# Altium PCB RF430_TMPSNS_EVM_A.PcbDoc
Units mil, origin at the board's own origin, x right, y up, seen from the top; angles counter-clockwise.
Board outline 1256 x 1256 mil, 2 copper layers (Top Layer, Bottom Layer), stack 62 mil thick; 41 components, 25 nets, 78 pads, 14 vias.
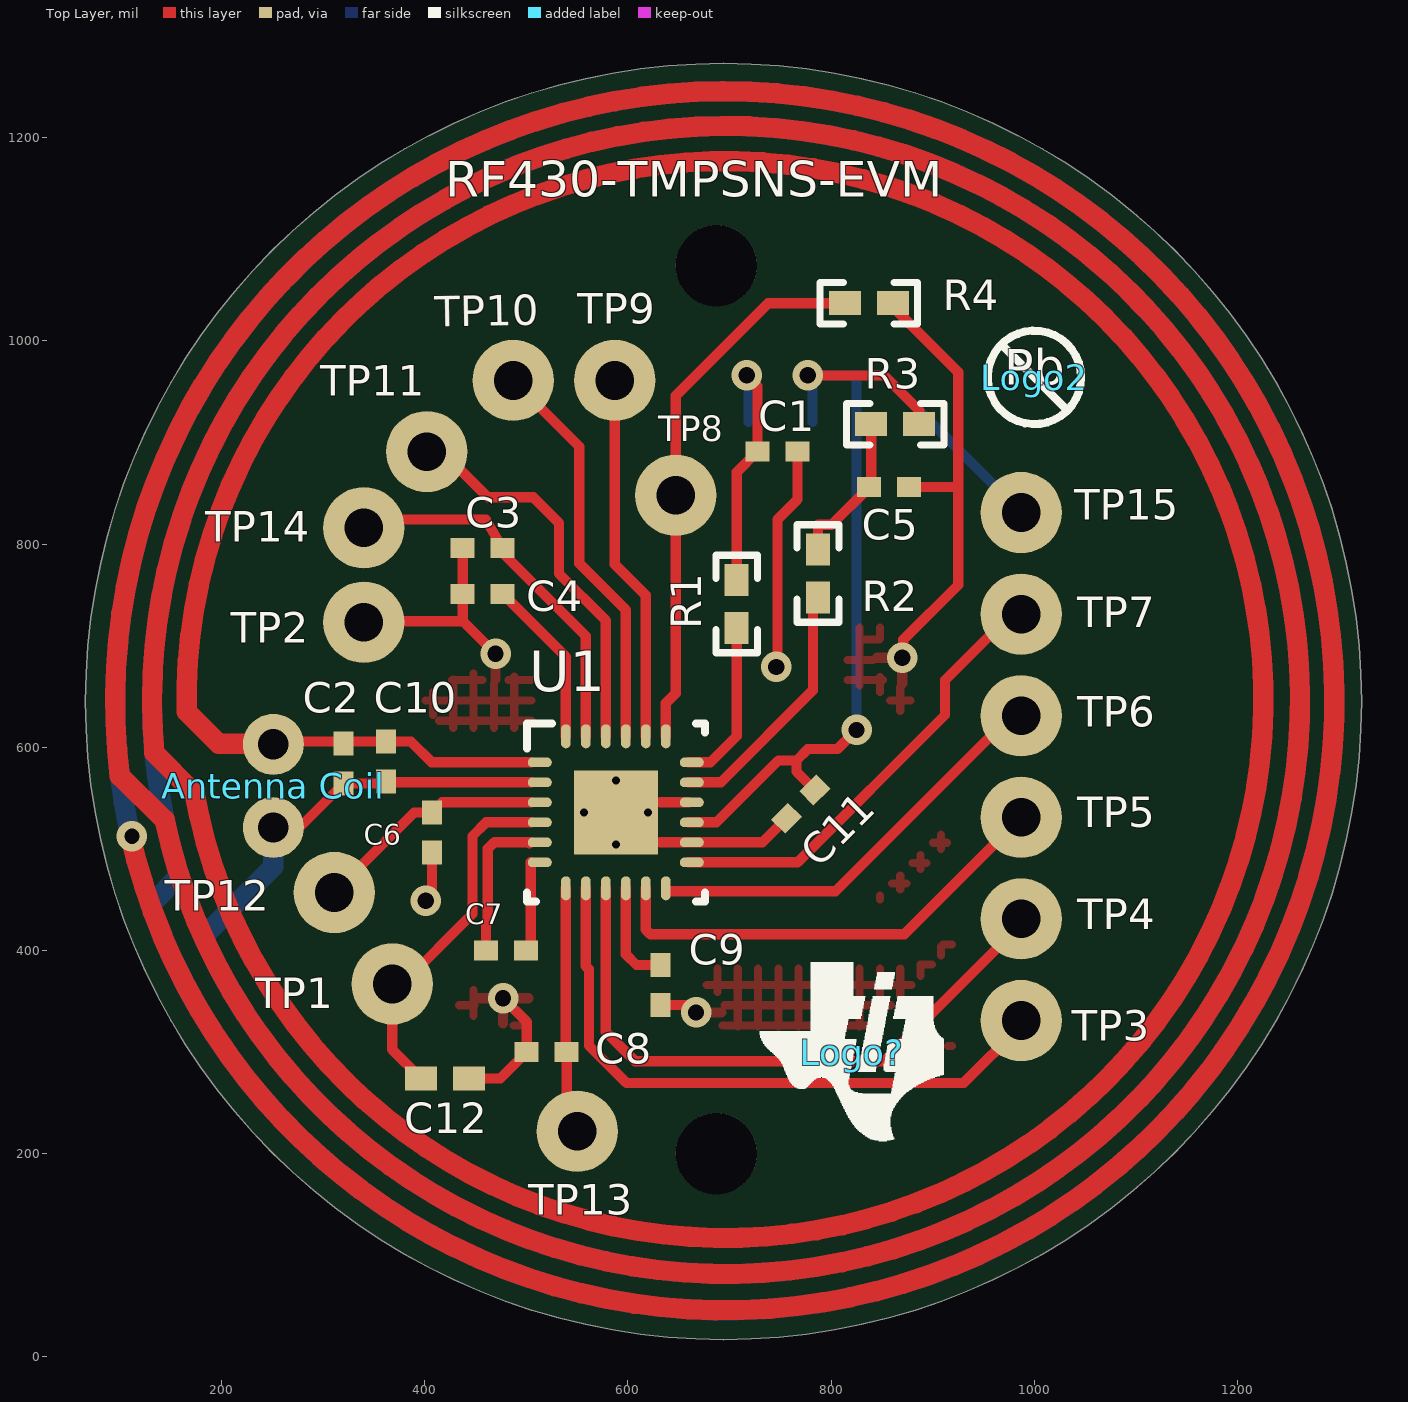
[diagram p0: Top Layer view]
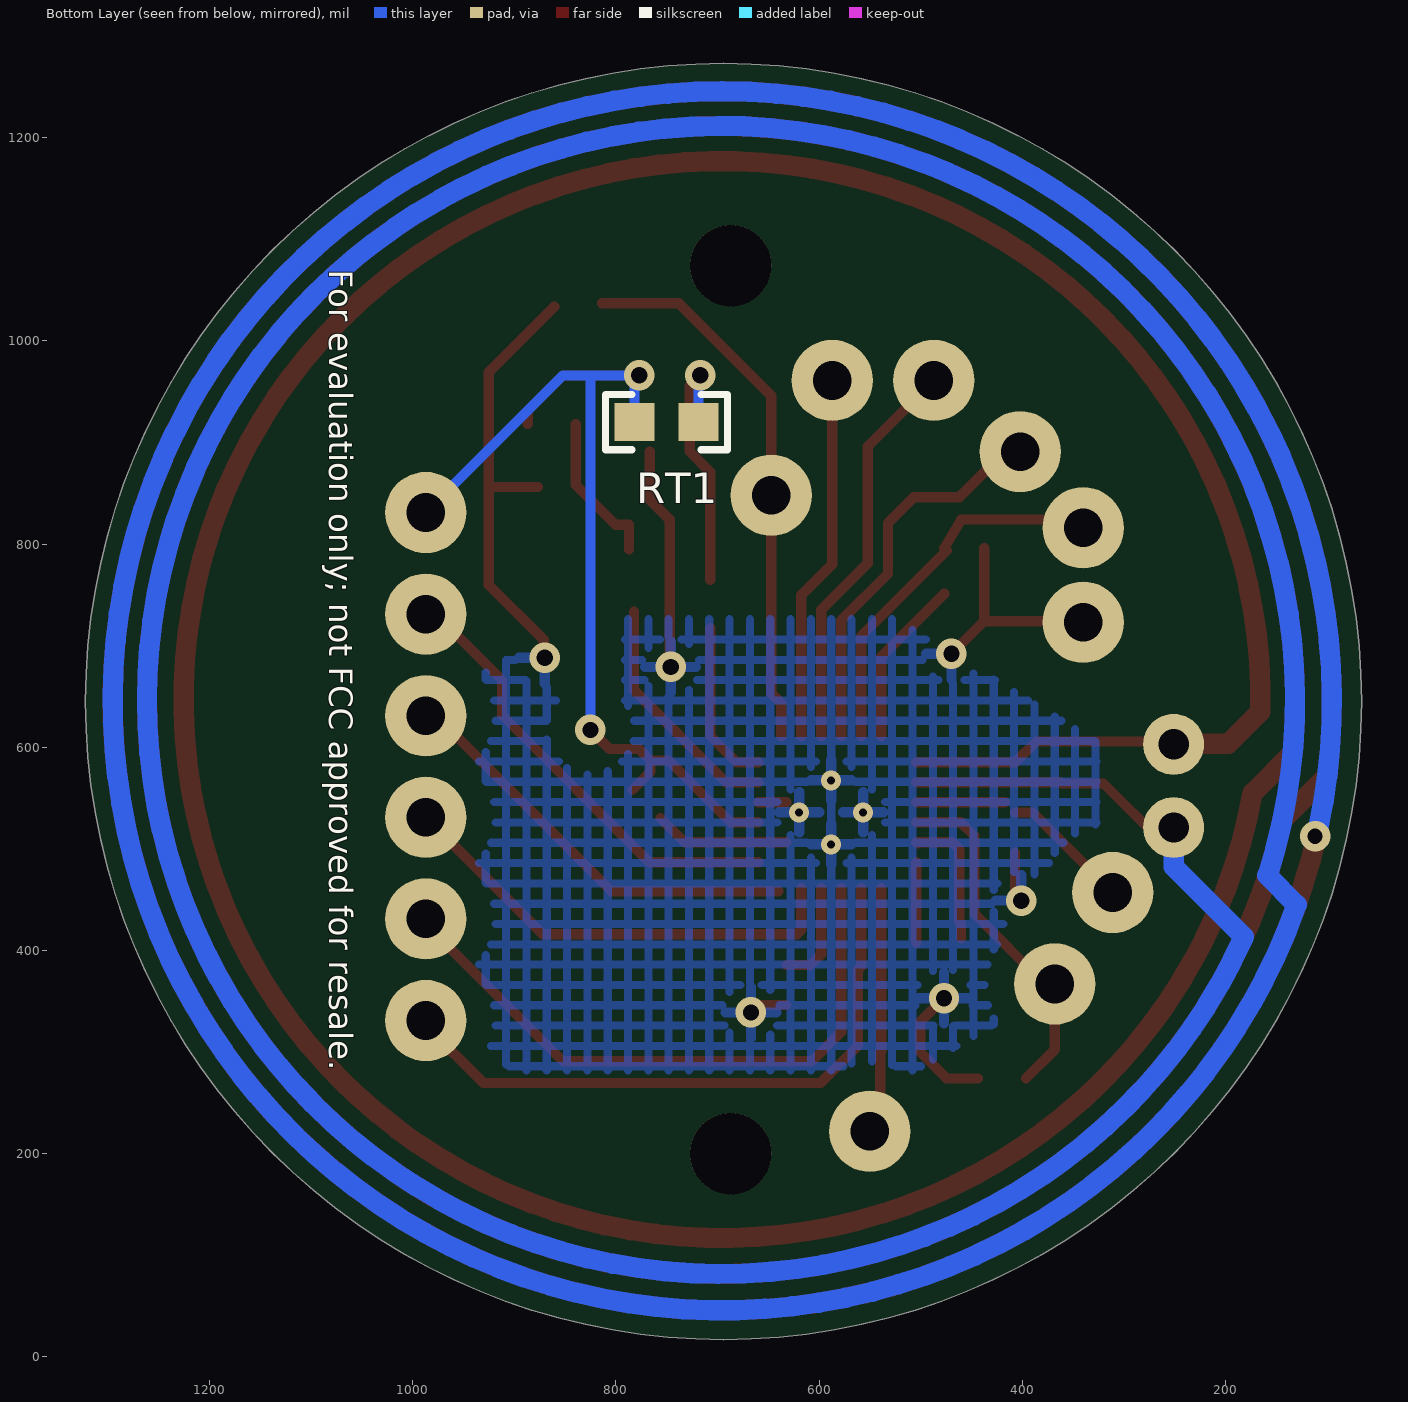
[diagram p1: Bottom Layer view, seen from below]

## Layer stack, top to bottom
Top Solder: solder mask 0.4, Solder Resist, Dk 3.5
Top Layer: signal copper 1.4
Dielectric1: core 59.2, FR-4, Dk 4.8
Bottom Layer: signal copper 1.4
Bottom Solder: solder mask 0.4, Solder Resist, Dk 3.5

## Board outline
694.02,17 cw(c694.02,645) 66.02,645 cw(c694.02,645) 694.02,1273 cw(c694.02,645) 1322.02,645 cw(c694.02,645)

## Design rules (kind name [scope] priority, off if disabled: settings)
AcuteAngle [All] p1: minimum=4.50000000000000E+0001 checktracksonly=FALSE
AssemblyTestPointUsage [All] p1: valid=2
BoardOutlineClearance BoardOutlineClearance_MountingHoles [OnCopper and InComponentClass('Mounting Holes')] p1: gap=40
BoardOutlineClearance BoardOutlineClearance_Poly [OnCopper and InPoly] p2: gap=25
BoardOutlineClearance [OnCopper and Not InComponentClass('Logo') and not InComponentClass('FiducialMark') and not InRegion(1000,500,4000,800)] p3: gap=15
Clearance Clearance_Keepouts [((IsTrack Or IsArc) And Not InPoly) And IsFree and IsKeepOut vs ((IsTrack Or IsArc) And Not InPoly) And IsFree and IsKeepOut] p1: gap=0
Clearance Clearance_Poly [InPolygon] p2: gap=25
Clearance [All] p3: gap=5
ComponentClearance ComponentClearance_MountingHoles_FiducialMarks [InComponentClass('Mounting Holes') vs InComponentClass('FiducialMark')] p1: gap=50 collisioncheckmode=3 verticalgap=10 showdistances=FALSE
ComponentClearance ComponentClearance_Shunt [InComponentClass('Header') vs InComponentClass('Shunt')] p2: gap=0 collisioncheckmode=3 verticalgap=0 showdistances=FALSE
ComponentClearance ComponentClearance_Logo [InComponentClass('Logo')] p3 off: gap=10 collisioncheckmode=3 verticalgap=10 showdistances=FALSE
ComponentClearance ComponentClearance_ScrewToNut [(HasFootprint('NY PMS 440 0025 PH')) vs (HasFootprint('Keystone_1902C'))] p4: gap=5 collisioncheckmode=3 verticalgap=10 showdistances=FALSE
ComponentClearance ComponentClearance_MountingHoles [InComponentClass('Mounting Holes')] p5: gap=250 collisioncheckmode=3 verticalgap=100000 showdistances=FALSE
ComponentClearance ComponentClearance_SmallPassives [HasFootprint('0201*') or HasFootprint('0402*') or HasFootprint('0508') or HasFootprint('0603*') or HasFootprint('0612') or HasFootprint('0805*') or HasFootprint('0815*') or HasFootprint('0830*') or HasFootprint('1206*') or HasFootprint('1210*') or HasFootprint('1808*') or HasFootprint('1812*') or HasFootprint('1825*') or HasFootprint('2010*') or HasFootprint('2220*') or HasFootprint('2225*') or HasFootprint('2512*') or HasFootprint('2728*') or HasFootprint('3518*') vs HasFootprint('0201*') or HasFootprint('0402*') or HasFootprint('0508') or HasFootprint('0603*') or HasFootprint('0612') or HasFootprint('0805*') or HasFootprint('0815*') or HasFootprint('0830*') or HasFootprint('1206*') or HasFootprint('1210*') or HasFootprint('1808*') or HasFootprint('1812*') or HasFootprint('1825*') or HasFootprint('2010*') or HasFootprint('2220*') or HasFootprint('2225*') or HasFootprint('2512*') or HasFootprint('2728*') or HasFootprint('3518*')] p6: gap=14.96 collisioncheckmode=3 verticalgap=10 showdistances=FALSE
ComponentClearance ComponentClearance_THtoSMT [IsThruComponent vs IsSMTComponent] p7 off: gap=3 collisioncheckmode=3 verticalgap=30 showdistances=TRUE
ComponentClearance ComponentClearance_THtoTH [IsThruComponent vs IsThruComponent] p8 off: gap=5 collisioncheckmode=3 verticalgap=30 showdistances=FALSE
ComponentClearance [All] p9 off: gap=30 collisioncheckmode=3 verticalgap=10 showdistances=FALSE
DiffPairsRouting [All] p1: maxlimit=100 minlimit=10 mostfreqgap=10 toplayer_minwidth=15 toplayer_maxwidth=15 toplayer_prefwidth=15 bottomlayer_minwidth=15 bottomlayer_maxwidth=15 bottomlayer_prefwidth=15 maxuncoupledlength=1000
FabricationTestPointUsage TestPointUsage [All] p1: valid=2 allowmultiple=FALSE
FabricationTestpoint Testpoint [All] p1: side=3 testpointundercomponent=TRUE minsize=40 maxsize=100 preferedsize=60 minholesize=0 maxholesize=40 preferedholesize=32 testpointgrid=1 allowsidetop=TRUE allowsidebottom=TRUE usegrid=TRUE gridtolerance=0.01
FanoutControl Fanout_LCC [IsLCC] p1: bgadir=Out bgaviamode=Centered fanoutstyle=Auto fanoutdirection=Alternating viagrid=1 // Fanout_LCC (Default Rule)
FanoutControl Fanout_BGA [IsBGA] p2: bgadir=Out bgaviamode=Centered fanoutstyle=Auto fanoutdirection=Alternating viagrid=1 // Fanout_BGA (Default Rule)
FanoutControl Fanout_Default [All] p4: bgadir=Out bgaviamode=Centered fanoutstyle=Auto fanoutdirection=Alternating viagrid=1 // Fanout_Default (Default Rule)
FanoutControl Fanout_Small [(CompPinCount < 5)] p5: bgadir=Out bgaviamode=Centered fanoutstyle=Auto fanoutdirection=OutThenIn viagrid=1 // Fanout_Small (Default Rule)
HoleSize [All] p1: absolutevalues=TRUE maxlimit=251 minlimit=7.87 maxpercent=80.000 minpercent=20.000
MinimumAnnularRing MinimumAnnularRing_ThermalPadVias [IsVia and InAnyComponent] p1: minimumring=5
MinimumAnnularRing [All] p2: minimumring=5
MinimumSolderMaskSliver MinimumSolderMaskSliver_Logo [InComponentClass('Logo') vs InComponentClass('Logo')] p1: minsoldermaskwidth=0.7
MinimumSolderMaskSliver [All] p2: minsoldermaskwidth=4
PlaneConnect [All] p1: planeconnectstyle=Relief reliefexpansion=10 reliefentries=4 reliefconductorwidth=10 reliefairgap=10
PolygonConnect [All] p1: connectstyle=Relief reliefconductorwidth=10 reliefentries=4 polygonreliefangle="90 Angle" airgapwidth=10
RoutingVias ThermalPadVias [IsVia and InAnyComponent] p1: holewidth=7.87 width=19.68 viastyle="Through Hole" minholewidth=7.87 minwidth=19.68 maxholewidth=15 maxwidth=35
RoutingVias [All] p2: holewidth=16 width=34 viastyle="Through Hole" minholewidth=7.87 minwidth=26 maxholewidth=40 maxwidth=65
SilkToBoardRegionClearance [Not ((IsComment or IsDesignator) And (Hide <> 'False')) and not InRegion(1000,500,4000,800)] p1:
SilkToSilkClearance SilkToSilkClearance_Pb-FreeLogo [(HasFootprint('Pb-Free_Overlay_Medium') OR HasFootprint('Pb-Free_Overlay_Small')) vs (HasFootprint('Pb-Free_Overlay_Medium') OR HasFootprint('Pb-Free_Overlay_Small'))] p1: silktosilkclearance=0
SilkToSilkClearance [All] p2: silktosilkclearance=3
SilkToSolderMaskClearance SilkToComponentPadClearance [IsPad and InAnycomponent] p1: minsilkscreentomaskgap=3 clearancetoexposedcopper=TRUE
SilkToSolderMaskClearance "Silk to Solder Mask Opening" [All] p2: minsilkscreentomaskgap=3 clearancetoexposedcopper=FALSE
SolderMaskExpansion [All] p1: expansion=1.97
Width [All] p1: maxlimit=100 minlimit=6 preferedwidth=10 checkconnectedcopper=TRUE
15 further rules are at their usual default settings.

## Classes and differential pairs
component class TIDM-TEMPSENSE: "Antenna Coil" C1 C2 C3 C4 C5 C6 C7 C8 C9 C10 C11 C12 R1 R2 R3 R4 RT1 TP1 TP2 TP3 TP4 TP5 TP6 TP7 TP8 TP9 TP10 TP11 TP12 TP13 TP14 TP15 U1
component class Logo: Logo?
component class TIDM-TEMPSENSE_Hardware: Logo2 Logo3 Logo? ZZ1 ZZ2 ZZ3 ZZ4
component class AssemblyNote: ZZ1 ZZ2 ZZ3 ZZ4

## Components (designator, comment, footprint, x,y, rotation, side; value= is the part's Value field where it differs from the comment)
"Antenna Coil" "Antenna Coil" PCBComponent_1 696,646 r0 top
C1 "C1005C0G1H220J050BA" 0402#1 747,891 r0 top
C2 "GRM1555C1E3R9CA01D" 0402#1 320,584 r270 top
C3 "885012205037" 0402#1 457,796 r0 top
C4 "885012205037" 0402#1 457,751 r0 top
C5 "C1005C0G1H220J050BA" 0402#1 857,856 r0 top
C6 "C1005X5R1A225K050BC" 0402#1 407,516 r90 top
C7 "885012205031" 0402#1 480,400 r0 top
C8 "885012205037" 0402#1 520,300 r0 top
C9 "885012205037" 0402#1 632,366 r90 top
C10 "GRM1555C1E330JA01D" 0402#1 362,586 r270 top
C11 "C1005X7S1A105K050BC" 0402#1 770,544 r45 top
C12 "885012205037" 0402#2 420,274 r0 top
Logo2 "Pb-Free Symbol" Pb-Free_Overlay_Small 1000,964 r0 top
Logo3 "FCC disclaimer" FCC_disclaimer 690,2314 r0 top
Logo? "Texas Instruments" TI_Symbol_Overlay_Small 820,300 r0 top
R1 "CRCW04021K00FKED" 0402#2 707,741 r90 top
R2 "CRCW04021K00FKED" 0402#2 787,771 r90 top
R3 "CRCW0402100KJNED" 0402#2 863,918 r180 top
R4 "CRCW040210K0JNED" 0402#2 837,1037 r180 top
RT1 "ERT-J1VS104FA" 0603 750,920 r180 bottom
TP1 "TESTPOINT" TESTPOINT#1 368,367 r0 top
TP2 "TESTPOINT" TESTPOINT#2 339,723 r0 top
TP3 "TESTPOINT" TESTPOINT#3 987,326 r90 top
TP4 "TESTPOINT" TESTPOINT#4 987,431 r90 top
TP5 "TESTPOINT" TESTPOINT#5 987,541 r90 top
TP6 "TESTPOINT" TESTPOINT#6 987,646 r90 top
TP7 "TESTPOINT" TESTPOINT#7 987,751 r0 top
TP8 "TESTPOINT" TESTPOINT#4 647,848 r90 top
TP9 "TESTPOINT" TESTPOINT#4 587,961 r90 top
TP10 "TESTPOINT" TESTPOINT#3 487,956 r90 top
TP11 "TESTPOINT" TESTPOINT#4 402,891 r90 top
TP12 "TESTPOINT" TESTPOINT#4 311,457 r90 top
TP13 "TESTPOINT" TESTPOINT#4 550,222 r90 top
TP14 "TESTPOINT" TESTPOINT#4 340,816 r90 top
TP15 "TESTPOINT" TESTPOINT#8 993,853 r90 top
U1 "RF430FRL152HCRGER" RGE0024C 588,535.95 r0 top
ZZ1 "This Assembly Note is for PCB labels only" AssemblyNoteLabel 185,3938 r0 top
ZZ2 "These assemblies are ESD sensitive, ESD precautions shall be observed." AssemblyNote 185,3829.11 r0 top
ZZ3 "These assemblies must be clean and free from flux and all contaminants. Use of no clean flux is not acceptable." AssemblyNote 185,3740.56 r0 top
ZZ4 "These assemblies must comply with workmanship standards IPC-A-610 Class 2, unless otherwise specified." AssemblyNote 185,3652 r0 top

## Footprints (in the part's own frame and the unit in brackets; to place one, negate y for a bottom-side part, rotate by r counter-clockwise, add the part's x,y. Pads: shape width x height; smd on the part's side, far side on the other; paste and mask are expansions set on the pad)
0402#1 [mm] "Chip Capacitor, Body 1.0x0.5mm, IPC High Density"
  rect 0.6x0.5 smd: 1(-0.5,0) 2(0.5,0)
  body extent -0.55,-0.3 0.55,0.3, height 1.3
0402#2 [mm] "0402 from SM-752 data"
  rect 0.8x0.6 smd: 1(-0.6,0) 2(0.6,0)
  body extent -0.55,-0.3 0.55,0.3, height 0.6
0603 [mm] "0603 from SM-752 data"
  rect 1x0.95 smd: 1(-0.8,0) 2(0.8,0)
  silkscreen extent -1.52,-0.69 1.52,0.69, body extent -0.87,-0.47 0.87,0.47, height 1
AssemblyNote [mil] "Assembly Note"
AssemblyNoteLabel [mil] "Assembly Note for PCB Labels"
FCC_disclaimer [mil]
Pb-Free_Overlay_Small [mil]
  silkscreen extent -46,-46 46,46
PCBComponent_1 [mil]
  round 60 hole 30: 1(-445,-43.17) 2(-445,-125)
  Top Layer lines w15: -460.26,-42.5 -452.3,-50.46
  Top Layer lines w20: -596.14,-74.45 cw(c-0.75,-0.24) -586.28,-131.22 ; -595.62,-74.38 -552.64,-117.36 ; -562.45,-51.55 -523.17,-90.83 ; -562.13,-51.23 cw(c0.5,0.5) -552.1,-117.24 ; -530.41,-11.29 cw(c-0.55,0.93) -522.57,-90.73 ; -530.21,-11.29 -499,-42.5 -460.26,-42.5
  Bottom Layer lines w20: -587.16,-127.22 cw(c-0.74,-0.28) -566.17,-201 ; -565.92,-200.92 -537,-172 ; -537.48,-172.15 cw(c0.49,0.54) -514.14,-232.66 -445,-163.52 -445,-125
RGE0024C [mm] "QFN, 24-Leads, Body 4x4mm, Pitch 0.5mm, Thermal Pad 2.1x2.1mm"
  oval 0.6x0.24 smd mask+0.025: 1(-1.9,1.25) 2(-1.9,0.75) 3(-1.9,0.25) 4(-1.9,-0.25) 5(-1.9,-0.75) 6(-1.9,-1.25) 13(1.9,-1.25) 14(1.9,-0.75) 15(1.9,-0.25) 16(1.9,0.25) 17(1.9,0.75) 18(1.9,1.25)
  oval 0.24x0.6 smd mask+0.025: 7(-1.25,-1.9) 8(-0.75,-1.9) 9(-0.25,-1.9) 10(0.25,-1.9) 11(0.75,-1.9) 12(1.25,-1.9) 19(1.25,1.9) 20(0.75,1.9) 21(0.25,1.9) 22(-0.25,1.9) 23(-0.75,1.9) 24(-1.25,1.9)
  rect 2.1x2.1 smd paste-1.05: 25(0,0)
  silkscreen extent -2.22,-2.22 2.22,2.22, body extent -2.07,-2.07 2.07,2.07, height 1.01
TESTPOINT#1 [mil]
  round 80 hole 37.99 paste+5: 1(0,0)
TESTPOINT#2 [mil]
  round 80 hole 37.99: 1(1,0)
TESTPOINT#3 [mil]
  round 80 hole 37.99: 1(5,0)
TESTPOINT#4 [mil]
  round 80 hole 37.99: 1(0,0)
TESTPOINT#5 [mil]
  round 80 hole 37.99: 1(-10,0)
TESTPOINT#6 [mil]
  round 80 hole 37.99: 1(-15,0)
TESTPOINT#7 [mil]
  round 80 hole 37.99: 1(0,-20)
TESTPOINT#8 [mil]
  round 80 hole 37.99: 1(-22,6)
TI_Symbol_Overlay_Small [mil]
  silkscreen extent -90,-88 91,88

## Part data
"Antenna Coil": library part Component_1
C1 C5: "CAP, CERM, 22 pF, 50 V, +/- 5%, C0G/NP0, 0402"
C2: "CAP, CERM, 3.9 pF, 25 V, +/- 5%, C0G/NP0, 0402"
C3 C4 C8 C9 C12: "CAP, CERM, 0.1 µF, 16 V, +/- 10%, X7R, 0402"
C6: "CAP, CERM, 2.2 µF, 10 V, +/- 10%, X5R, 0402"
C7: "CAP, CERM, 0.01 µF, 16 V, +/- 10%, X7R, 0402"
C10: "CAP, CERM, 33 pF, 25 V, +/- 5%, C0G/NP0, 0402"
C11: "CAP, CERM, 1 µF, 10 V, +/- 10%, X7S, 0402"
Logo2: library part Pb-Free
Logo3: library part FCC_disclaimer, "FCC_disclaimer"
Logo?: library part TI_Logo, "Texas Instrument Corporate Signature"
R1 R2: "RES, 1.00 k, 1%, 0.063 W, 0402"
R3: "RES, 100 k, 5%, 0.063 W, 0402"
R4: "RES, 10 k, 5%, 0.063 W, 0402"
RT1: "Thermistor NTC, 100k ohm, 1%, 0603"
TP1 TP2 TP3 TP4 TP5 TP6 TP7 TP8 TP9 TP10 TP11 TP12 TP13 TP14 TP15: "TEST POINT.  No entry in BOM."
U1: "NFC ISO 15693 Sensor Transponder, RGE0024C"
ZZ1: library part AssemblyNoteLabel
ZZ2 ZZ3 ZZ4: library part AssemblyNote

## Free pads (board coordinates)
  round 80 hole 80: 0(687,200) 0(687,1074)

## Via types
v1: diameter 30, hole 16, Top Layer to Bottom Layer, 9 vias
v2: diameter 19.68, hole 7.87, Top Layer to Bottom Layer, 4 vias
v3: diameter 30, hole 15, Top Layer to Bottom Layer, 1 vias

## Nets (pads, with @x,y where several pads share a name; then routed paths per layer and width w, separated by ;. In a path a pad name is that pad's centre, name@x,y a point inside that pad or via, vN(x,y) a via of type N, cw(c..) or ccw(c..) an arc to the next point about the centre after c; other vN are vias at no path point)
ADC0: TP7.1 U1.13 | length 452.6
  Top Layer w10: U1.13@659.76,486.79 767,486.79 912,631.79 912,666 TP7.1@987,741
ANT1: "Antenna Coil.1" C2.1 C10.1 U1.1 | length 250.4
  Top Layer w10: 262.36,605.68 C10.1 386.32,605.68 406.79,585.21 U1.1@504.24,585.21
ANT2: "Antenna Coil.2" C2.2 C10.2 U1.2 | length 264.2
  Top Layer w10: 263.81,508.13 C2.2 361.57,564.31 362.79,565.53 U1.2@504.24,565.53
FLYING_CAP_T1: C7.1 U1.5 | length 135.5
  Top Layer w10: 460.39,411.92 460.39,426.57 462,428.18 462,500 468.47,506.47 504.24,506.47 U1.5@502.94,505.17
FLYING_CAP_T2: C7.2 U1.6 | length 79.3
  Top Layer w10: C7.2@504.24,407.44 U1.6@504.24,486.79
GND: C1.2 C3.1 C4.1 C5.2 C6.1 C8.1 C9.1 C11.1 C12.2 R4.1 TP2.1 U1.14 U1.16 U1.25 | length 1238.7
  Top Layer w10: TP2.1@340,724 437.02,724 437.31,724.3 ; v1@407,455 C6.1 ; C3.1 C4.1 437.32,724.3 ; C12.2 474.32,274 C8.1 500.31,329.69 v1(477,353) ; v1(469.63,691.98) 437.31,724.3 ; C9.1 v1@659.68,346.32 ; 632,506.47 659.76,506.47 732.47,506.47 C11.1 ; 632,545.84 U1.16@659.76,545.84 ; v1@747,679 747,824 766.68,843.68 C1.2 ; R4.1@860.62,1033.59 925,969.21 925,856 ; v1@871,688 871,705.71 925,759.71 925,856 ; C5.2 925,856
  other v1: 667,339 401,449 746,679 870,688
  other v2: 588,504.45 556.5,535.95 619.5,535.95 588,567.45
NetC1_1: C1.1 R1.2 RT1.2 | length 258.6
  Top Layer w10: R1.2 707,870.69 C1.1 727.32,955.68 v1(717,966)
  Bottom Layer w10: RT1.2 v1@718.5,964.5
NetC4_2: C4.2 U1.24 | length 166
  Top Layer w10: C4.2 538.79,688.9 U1.24
NetC5_1: C5.1 R2.2 R3.2 | length 152.9
  Top Layer w10: R2.2 787,819 800.31,819 C5.1 839.38,858.06 R3.2
NetC9_2: C9.2 U1.10 | length 103.5
  Top Layer w10: U1.10 597.84,396.16 608.32,385.68 C9.2
P1.0/MOSI/SDA: TP6.1 U1.12 | length 422.6
  Top Layer w10: U1.12@640.12,458.24 804.24,458.24 TP6.1@987,641
P1.1/MISO/SCL: TP5.1 U1.11 | length 459.6
  Top Layer w10: U1.11 617.53,420.47 622,416 872,416 TP5.1
P1.2/SPI_CLK: TP4.1 U1.9 | length 618
  Top Layer w10: U1.9 578.16,319.84 607,291 852,291 TP4.1@987,426
P1.3/SPI_CS: TP3.1 U1.8 | length 620
  Top Layer w10: U1.8 558.47,384.53 561.5,381.5 561.5,306.5 598.38,269.62 930.62,269.62 TP3.1@987,326
P1.4/TCK: TP11.1 U1.22 | length 408.6
  Top Layer w10: TP11.1@392,916 462,846 506.84,846 532,820.84 532,771 578.16,724.84 U1.22
P1.5/TDI: TP10.1 U1.21 | length 396.2
  Top Layer w10: TP10.1 552,896 552,781 597.84,735.16 U1.21
P1.6/TDO: TP9.1 U1.20 | length 357
  Top Layer w10: TP9.1@577,951 587,941 587,780.07 617.53,749.54 U1.20
P1.7/TMS: R4.2 TP8.1 U1.19 | length 543.4
  Top Layer w10: U1.19 637.21,643.21 647,653 TP8.1 647,946 738,1037 R4.2
SENSOR_REFERENCE_POTENTIAL: C11.2 R3.1 RT1.1 TP15.1 U1.15 | length 1028.2
  Top Layer w10: U1.15@659.76,526.16 687.16,526.16 748,587 765.87,587 ; v1(777,966) 852,966 886.62,931.38 R3.1 ; C11.2 765.87,575.96 765.87,587 ; v1(825,617) 806.1,598.1 776.98,598.1 765.87,587
  Bottom Layer w10: v1(777,966) 852,966 TP15.1 ; RT1.1 v1@781.5,961.5 ; v1(825,617) 825,961
SKIN_TEMPERATURE_REFERENCE: R2.1 U1.17 | length 237
  Top Layer w10: U1.17@659.76,565.53 691.53,565.53 782,656 R2.1@782,733.28
SKIN_TEMPERATURE_THERMISTER: R1.1 U1.18 | length 164.3
  Top Layer w10: U1.18@659.76,585.21 681.21,585.21 707,611 R1.1
VDD2X: C8.2 TP13.1 U1.7 | length 255.2
  Top Layer w10: TP13.1@523.81,209.36 523.81,237.72 TP13.1@534.28,248.19 ; C8.2@538.79,300.9 U1.7 ; TP13.1@539.68,248.19 C8.2
VDDB: C12.1 TP1.1 U1.4 | length 341.8
  Top Layer w10: TP1.1 368,302.38 C12.1 ; TP1.1@378,367 447,436 447,512.69 460.47,526.16 U1.4@504.24,526.16
VDDH: C3.2 TP14.1 U1.23 | length 367
  Top Layer w10: TP14.1@343.32,824 460,824 C3.2 ; C3.2@474.34,793.66 558.47,709.53 U1.23
VDDSW: C6.2 TP12.1 U1.3 | length 215.7
  Top Layer w10: TP12.1 389.69,535.69 C6.2 ; 417.16,545.84 U1.3@504.24,545.84
copper on no net:
  other v3: 111.72,512.28

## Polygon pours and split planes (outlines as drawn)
GND on Bottom Layer "Top Layer-No Net" (hatched 90Degree grid 20 track 8, pour order 0): 506.47,282 898.48,282 1026,359.84 1021.28,362.73 1021.28,616.44 851.25,720.23 841.8,726 586.76,726 525.36,726 412.01,656.81 327,604.91 327,385.79
GND on Top Layer "Top Layer-GND" (hatched 90Degree grid 20 track 8, pour order 2): 348.14,388.05 361.85,388.05 521.78,291 901.05,291 914.76,291 1024.43,357.55 1029,360.32 1029,612.64 1024.43,612.64 850.79,718 540.06,718 512.64,718 339,612.64 343.57,609.86 343.57,390.82

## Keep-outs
Keep-Out Layer:
  text ".Layer_Name" at 577,-858.49 h60

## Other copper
Top Layer:
  text ".Layer_Name" at 577,-858.49 h60
Bottom Layer:
  text ".Layer_Name" at 577,-858.49 h60

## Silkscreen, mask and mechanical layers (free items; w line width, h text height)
Top Overlay:
  text "RF430-TMPSNS-EVM" at 420,1130 h60
  text ".Layer_Name" at 577,-858.49 h60
Bottom Overlay:
  text ".Layer_Name" at 577,-858.49 h60
Top Paste:
  text ".Layer_Name" at 577,-858.49 h60
Bottom Paste:
  text ".Layer_Name" at 577,-858.49 h60
Top Solder:
  text ".Layer_Name" at 577,-858.49 h60
  text ".Layer_Name" at 577,-858.49 h60
Bottom Solder:
  text ".Layer_Name" at 577,-858.49 h60
Drill Guide:
  text ".Layer_Name" at 577,-858.49 h60
M1 Board Outline:
  circle w10: c694.02,645 r628
  text ".Layer_Name" at 577,-858.49 h60
M2 Board Dimensions:
  rectangle: 0,-275 125,-150
  rectangle: 125,-400 500,-275
  lines w7: 0,-275 1000,-275 ; 125,-400 125,-150 ; 250,-400 250,-150 ; 500,-400 500,-150 ; 750,-400 750,-150 ; 0,-400 1000,-400 1000,-150 0,-150 0,-400
  text ".Layer_Name" at 577,-858.49 h60
M3 3D STEP Top:
  text ".Layer_Name" at 577,-858.49 h60
M4 3D STEP Bottom:
  text ".Layer_Name" at 577,-858.49 h60
M5 Assembly Top:
  lines w10: -292,-930.17 6308,-930.17 ; -292,-726.83 6310,-726.83 ; -292,-523.5 -292,-1133.5 3713,-1133.5 6310,-1133.5 6310,-523.5 -291.5,-523.5 -291.5,-1133.5 1284,-1133.5 ; 2173,-1133.5 2173,-523.5 ; 3440,-726.83 3440,-523.5 ; 4280,-726.83 4280,-523.5 ; 4902,-1140 4902,-937.17
  text "COMPONENTS MARKED 'DNP' SHOULD NOT BE POPULATED." at 1153.5,-318.5 h60
  text "ASSEMBLY VARIANT:" at 1153,-434 h60
  text ".VariantName" at 2189,-434 h60
  text "PCB VIEWED FROM TOP SIDE" at -228.5,-655.67 h60
  text "BOARD #:" at 2248,-655.67 h60
  text ".PRJ_Number" at 2793.5,-655.67 h60
  text "REV:" at 3638,-655.67 h60
  text ".PCB_Rev" at 3929.5,-655.67 h60
  text "SVN REV:" at 4476,-655.67 h60
  text ".VersionControl_RevNumber" at 4982,-655.67 h60
  text "TID #:" at 2248,-859 h60
  text ".TID" at 2793.5,-859 h60
  text "PLOT NAME =" at -228.5,-1064.34 h60
  text ".plot_File_Name" at 577,-1064.34 h60
  text "GENERATED    :" at 2250,-1064.34 h60
  text ".Print_Date" at 3119.5,-1064.34 h60
  text ".Print_Time" at 3848.5,-1064.34 h60
  text "TEXAS INSTRUMENTS" at 5113,-1064.34 h60
M6 Assembly Bottom:
  lines w10: -292.5,-727.33 6309.5,-727.33 ; -290.5,-930.67 6309.5,-930.67 ; 1115.5,-1140.5 1115.5,-937.67 ; 1737.5,-727.33 1737.5,-524 ; 2577.5,-727.33 2577.5,-524 ; 3844.5,-1134 3844.5,-524 ; 4733.5,-1134 6309,-1134 6309,-524 -292.5,-524 -292.5,-1134 2304.5,-1134 6309.5,-1134 6309.5,-524
  text "COMPONENTS MARKED 'DNP' SHOULD NOT BE POPULATED." at 6102,-318 h60
  text ".VariantName" at 5058,-434 h60
  text "ASSEMBLY VARIANT:" at 6097,-434 h60
  text ".VersionControl_RevNumber" at 1035.5,-656.17 h60
  text "SVN REV:" at 1541.5,-656.17 h60
  text ".PCB_Rev" at 2088,-656.17 h60
  text "REV:" at 2379.5,-656.17 h60
  text ".PRJ_Number" at 3224,-656.17 h60
  text "BOARD #:" at 3769.5,-656.17 h60
  text "PCB VIEWED FROM BOTTOM SIDE" at 6246,-656.17 h60
  text ".TID" at 3224,-859.5 h60
  text "TID #:" at 3769.5,-859.5 h60
  text "TEXAS INSTRUMENTS" at 904.5,-1064.84 h60
  text ".Print_Time" at 2169,-1064.84 h60
  text ".Print_Date" at 2898,-1064.84 h60
  text "GENERATED    :" at 3767.5,-1064.84 h60
  text ".plot_File_Name" at 5440.5,-1064.84 h60
  text "PLOT NAME =" at 6246,-1064.84 h60
M9 Title Sheet:
  drawing of 57 lines, arcs and shapes, not listed
  text "1" at 739.84,8036.5 h70
  text "2" at 3235.5,8036.5 h70
  text "3" at 5724.84,8036.5 h70
  text "4" at 8231.51,8036.5 h70
  text "5" at 10730.5,8036.5 h70
  text "6" at 13235.5,8036.5 h70
  text "A" at -416.5,6893.5 h70
  text "A" at 14383.5,6893.5 h70
  text "B" at -416.5,4513.5 h70
  text "B" at 14383.5,4513.5 h70
  text "C" at -416.5,2138.5 h70
  text "C" at 14383.5,2138.5 h70
  text "PROJECT TITLE:" at 11343.5,277.5 h45
  text ".PRJ_Title" at 11393.5,144.17 h70
  text "DESIGNED FOR:" at 11343.5,-23.5 h45
  text ".PRJ_Customer" at 11393.5,-163.5 h70
  text "D" at -416.5,-231.5 h70
  text "D" at 14383.5,-231.5 h70
  text "FILE NAME:" at 11343.5,-323.5 h45
  text ".PCB_File_Name_No_Path" at 11393.5,-443.5 h70
  text "Texas Instruments (TI) and/or its licensors do not warrant the accuracy or completeness of this specification" at 6374,-605.34 h45
  text "ENGINEER:" at 11343.5,-613.5 h45
  text "LAYOUT BY:" at 12848.5,-613.5 h45
  text "or any information contained therein. TI and/or its licensors do not warrant that this design will meet" at 6329.01,-718 h45
  text ".PRJ_Engineer" at 11393.5,-768.49 h70
  text ".PCB_Layout" at 12899,-768.49 h70
  text "the specifications, will be suitable for your application or fit for any particular purpose, or will operate in" at 6329.01,-830.67 h45
  text ".Layer_Name" at 577,-858.49 h60
  text "ALTIUM DESIGNER VERSION:" at 12848.5,-923.5 h45
  text "an implementation. TI and/or its licensors do not warrant that the design is production worthy. You should" at 6329.01,-943.33 h45
  text "completely validate and test your design implementation to confirm the system functionality for your application." at 6374,-1056 h45
  text ".print_Scale" at 11393.5,-1056.83 h70
  text ".Application_BuildNumber" at 12899,-1056.83 h70
  text "1" at 739.84,-1263.5 h70
  text "2" at 3235.5,-1263.5 h70
  text "3" at 5724.84,-1263.5 h70
  text "4" at 8231.51,-1263.5 h70
  text "5" at 10730.5,-1263.5 h70
  text "6" at 13235.5,-1263.5 h70
M10 Fab Notes:
  drawing of 173 lines, arcs and shapes, not listed
  text "DESIGN INFORMATION" at 12378.02,6201 h60
  text "MIN. TRACK WIDTH:" at 11733.46,6021 h60
  text "8" at 12829.7,6021 h60
  text "MIL" at 12984.46,6021 h60
  text "MIN. CLEARANCE:" at 11733.46,5889 h60
  text "0.2" at 12769.7,5889 h60
  text "mm" at 12984.46,5889 h60
  text "MIN. VIA PAD SIZE:" at 11733.46,5757 h60
  text "24" at 12799.71,5757 h60
  text "MIL" at 12984.46,5757 h60
  text "0.05mm (2MIL)" at 12428.46,5615.29 h60
  text "MINIMUM ANNULAR RING" at 11404.23,5611 h60
  text "EXTERNAL" at 13136.46,5611 h60
  text "PER" at 11604.23,5493 h60
  text "IPC-D-275 CLASS 2 LEVEL C" at 11824.23,5493 h60
  text "MIL, HOLES" at 13312.46,5380.71 h60
  text "+/-" at 12920,5380 h60
  text "+/-" at 13774,5380 h60
  text "REGISTRATION TOLERANCES:" at 11404.23,5375 h60
  text "METAL" at 12604,5375 h60
  text "5" at 13180.2,5375 h60
  text "3" at 14013.2,5375 h60
  text "MIL" at 14129.46,5375 h60
  text "+/-" at 13774,5262 h60
  text "HOLE SIZE TOLERANCE (UNLESS OTHERWISE SPECIFIED):" at 11404.23,5257 h60
  text "3" at 14013.2,5257 h60
  text "MIL" at 14129.46,5257 h60
  text "MATERIAL:" at 11329.46,5047.54 h60
  text "FR-4 High Tg" at 12315.9,4907.21 h60
  text "FR-408" at 11750.46,4898.64 h60
  text "OTHER" at 13238.46,4898.64 h60
  text "X" at 12161,4895 h60
  text "62 MIL (1.6mm) +/-10%" at 12070.56,4735.92 h60
  text "THICKNESS:" at 11404.23,4731.64 h60
  text "X" at 11942.4,4731.64 h60
  text "OTHER" at 13355.46,4731.64 h60
  text "TOLERANCE:" at 11404.23,4573.64 h60
  text "X" at 12243.53,4573.64 h60
  text "ANSI IPC-6012 TYPE 3 CLASS 2" at 12430.48,4573.64 h60
  text "OTHER +/-" at 12430.46,4417.64 h60
  text "BOW & TWIST:" at 11404.23,4260.64 h60
  text "X" at 12243.53,4260.64 h60
  text "ANSI IPC-6012 TYPE 3 CLASS 2" at 12430.48,4260.64 h60
  text "OTHER +/-" at 12430.46,4102.13 h60
  text "DRILLING:" at 11329.46,3963.64 h60
  text "REFERENCE:" at 11404.23,3846.64 h60
  text "X" at 12052.46,3846.64 h60
  text "AS SHOWN" at 12239.46,3846.64 h60
  text "X" at 12953.46,3846.64 h60
  text "NC_DRILL FILES" at 13090.46,3846.64 h60
  text "PTH MIN COPPER THICKNESS:" at 11404.23,3688.64 h60
  text "X" at 12754.46,3688.64 h60
  text "1MIL" at 12891.46,3688.64 h60
  text "OTHER" at 13388.46,3688.64 h60
  text "BOARD FINISH:" at 11329.46,3529.64 h60
  text "SILKSCREEN:" at 11484.68,3411.64 h60
  text "X" at 12433.46,3411.64 h60
  text "TOP" at 12559.46,3411.64 h60
  text "X" at 12943.46,3411.64 h60
  text "BOTTOM" at 13070.46,3411.64 h60
  text "SILKSCREEN COLOR:" at 11484.68,3244.64 h60
  text "X" at 12432.42,3244.64 h60
  text "WHITE" at 12559.46,3244.64 h60
  text "OTHER" at 13070.46,3244.64 h60
  text "X" at 12563.42,3085.44 h60
  text "GREEN" at 12690.46,3085.44 h60
  text "OTHER" at 13308.46,3085.44 h60
  text "SOLDER RESIST COLOR:" at 11484.68,3074.64 h60
  text "X" at 12563.42,2915.44 h60
  text "MATTE" at 12690.46,2915.44 h60
  text "SEMI-GLOSS" at 13308,2914.8 h60
  text "IMMERSION GOLD (ENIG)" at 12390.46,2726.92 h60
  text "ENEPIG" at 13728,2723.64 h60
  text "SURFACE FINISH:" at 11329.46,2722.64 h60
  text "X" at 12203.51,2722.64 h60
  text "IMM. TIN/SILVER OR EQUIV" at 11659,2565.64 h60
  text "OTHER" at 13090.46,2565.64 h60
  text "ARRAY/PANEL:" at 11329.46,2386.64 h60
  text "CUT AND TRIM PER M1 BOARD OUTLINE" at 12390.46,2382.35 h60
  text "N.C. ROUTE" at 12390.46,2230.64 h60
  text "X" at 13069.46,2230.64 h60
  text "V. SCORE" at 13256.46,2230.64 h60
  text "CERTIFICATION:" at 11329.46,2093.64 h60
  text "MATERIALS AND WORKMANSHIP FOR ALL PCBS" at 12054.46,2093.64 h60
  text "TO MEET OR EXCEED THE REQUIREMENTS OF:" at 12054.46,1995.64 h60
  text "X" at 11680.96,1859.13 h60
  text "ANSI IPC-A-600F CLASS ->" at 11819.96,1859.13 h60
  text "X" at 13459.02,1859.13 h60
  text "2" at 13577.96,1859.14 h60
  text "1" at 13262.96,1857.64 h60
  text "3" at 13931.96,1857.64 h60
  text "X" at 12495.02,1699.64 h60
  text "RoHS" at 12631.96,1699.64 h60
  text "OTHER" at 13276.36,1699.64 h60
  text "PER ORDER" at 13673.42,1699.64 h60
  text "ALL BOARDS MUST MEET OR EXCEED UL94-V0 REQUIREMENTS." at 11357,1534 h60
  text "PCB MUST BEAR THE UL94V-0 UL REGISTERED MATERIAL ID NUMBER" at 11357,1414 h60
  text "ADDITIONAL REQUIREMENTS:" at 11329.46,1240.64 h60
  text "MICROSECTION:" at 11404.23,1125.64 h60
  text "YES" at 12309.96,1125.64 h60
  text "REQUIRED" at 13171.46,969.49 h60
  text "BARE BOARD ELEC. TEST:" at 11404.23,966.64 h60
  text "NONE" at 12709.96,966.64 h60
  text "X" at 13044.46,966.64 h60
  text "PER ORDER" at 13763.46,966.64 h60
  text ".Layer_Name" at 577,-858.49 h60
M11 Gerber Information:
  lines w10: -292,-930.17 6308,-930.17 ; -292,-726.83 6310,-726.83 ; -292,-523.5 -292,-1133.5 3713,-1133.5 6310,-1133.5 6310,-523.5 -291.5,-523.5 -291.5,-1133.5 1284,-1133.5 ; 2173,-1133.5 2173,-523.5 ; 3440,-726.83 3440,-523.5 ; 4280,-726.83 4280,-523.5 ; 4902,-1140 4902,-937.17
  text "ALL ARTWORK VIEWED FROM TOP SIDE" at -228.5,-655.67 h60
  text "BOARD #:" at 2248,-655.67 h60
  text ".PRJ_Number" at 2793.5,-655.67 h60
  text "REV:" at 3638,-655.67 h60
  text ".PCB_Rev" at 3929.5,-655.67 h60
  text "SVN REV:" at 4476,-655.67 h60
  text ".VersionControl_RevNumber" at 4982,-655.67 h60
  text "LAYER NAME =" at -228.5,-858.49 h60
  text "TID #:" at 2248,-859 h60
  text ".TID" at 2793.5,-859 h60
  text "PLOT NAME =" at -228.5,-1064.34 h60
  text ".plot_File_Name" at 577,-1064.34 h60
  text "GENERATED    :" at 2250,-1064.34 h60
  text ".Print_Date" at 3119.5,-1064.34 h60
  text ".Print_Time" at 3848.5,-1064.34 h60
  text "TEXAS INSTRUMENTS" at 5113,-1064.34 h60
M12 Stackup:
  drawing of 191 lines, arcs and shapes, not listed
  text "Layer" at 9790.34,7830 h60
  text "Name" at 10200.26,7830 h60
  text "Material" at 11130,7830 h60
  text "Thickness" at 11989.77,7830 h60
  text "Constant" at 12639.6,7830 h60
  text "Board Layer Stack" at 13209.46,7830 h60
  text "1" at 9790.34,7710 h60
  text "Top Overlay" at 10200.26,7710 h60
  text "2" at 9790.34,7590 h60
  text "Top Solder" at 10200.26,7590 h60
  text "Solder Resist" at 11130,7590 h60
  text "0.40mil" at 11989.77,7590 h60
  text "3.5" at 12639.6,7590 h60
  text "3" at 9790.34,7470 h60
  text "Top Layer" at 10200.26,7470 h60
  text "Copper" at 11130,7470 h60
  text "1.40mil" at 11989.77,7470 h60
  text "4" at 9790.34,7350 h60
  text "Dielectric1" at 10200.26,7350 h60
  text "FR-4" at 11130,7350 h60
  text "59.20mil" at 11989.77,7350 h60
  text "4.8" at 12639.6,7350 h60
  text "5" at 9790.34,7230 h60
  text "Bottom Layer" at 10200.26,7230 h60
  text "Copper" at 11130,7230 h60
  text "1.40mil" at 11989.77,7230 h60
  text "6" at 9790.34,7110 h60
  text "Bottom Solder" at 10200.26,7110 h60
  text "Solder Resist" at 11130,7110 h60
  text "0.40mil" at 11989.77,7110 h60
  text "3.5" at 12639.6,7110 h60
  text "7" at 9790.34,6990 h60
  text "Bottom Overlay" at 10200.26,6990 h60
  text ".Layer_Name" at 577,-858.49 h60
M13 Component Bodies Top:
  text ".Layer_Name" at 577,-858.49 h60
M14 Component Bodies Bottom:
  text ".Layer_Name" at 577,-858.49 h60
M15 Courtyards Top:
  text ".Layer_Name" at 577,-858.49 h60
M16 Courtyards Bottom:
  text ".Layer_Name" at 577,-858.49 h60
Drill Drawing:
  circle w10: c5348.65,3303.39 r22.05
  lines w10: 5326.6,2785.29 5348.65,2796.31 5370.7,2785.29 5359.68,2807.33 5370.7,2829.38 5348.65,2818.36 5326.6,2829.38 5337.63,2807.33 5326.6,2785.29 ; 5326.6,2884.5 5370.7,2884.5 5370.7,2928.59 5326.6,2928.59 5326.6,2884.5 ; 5326.6,2994.73 5337.63,2994.73 5348.65,2983.71 5359.68,2994.73 5370.7,2994.73 5359.68,3005.75 5370.7,3016.78 5359.68,3016.78 5348.65,3027.8 5337.63,3016.78 5326.6,3016.78 5337.63,3005.75 5326.6,2994.73 ; 5326.6,3082.92 5326.6,3093.94 5337.63,3104.97 5326.6,3115.99 5326.6,3127.01 5337.63,3127.01 5348.65,3115.99 5359.68,3127.01 5370.7,3127.01 5370.7,3115.99 5359.68,3104.97 5370.7,3093.94 5370.7,3082.92 5359.68,3082.92 5348.65,3093.94 5337.63,3082.92 5326.6,3082.92 ; 5326.6,3193.15 5337.63,3193.15 5337.63,3182.13 5359.68,3182.13 5359.68,3193.15 5370.7,3193.15 5370.7,3215.2 5359.68,3215.2 5359.68,3226.22 5337.63,3226.22 5337.63,3215.2 5326.6,3215.2 5326.6,3193.15
  lines w12: 5286,2755.52 8241.34,2755.52 ; 5286,3350.79 8241.34,3350.79 ; 5601.13,2656.31 5601.13,3450 ; 5917.88,2656.31 5917.88,3450 ; 6538.9,2656.31 6538.9,3450 ; 6782.83,2656.31 6782.83,3450 ; 7142.73,2656.31 7142.73,3450 ; 7851.88,2656.31 7851.88,3450 ; 5286,2656.31 8241.34,2656.31 8241.34,3450 5286,3450 5286,2656.31
  text "Symbol" at 5345.53,3380.55 h72
  text "Quantity" at 5630.9,3380.55 h72
  text "Finished Hole Size" at 5947.64,3380.55 h72
  text "Plated" at 6568.66,3380.55 h72
  text "Hole Type" at 6812.59,3380.55 h72
  text "Drill Layer Pair" at 7172.49,3380.55 h72
  text "Tolerance" at 7881.64,3380.55 h72
  text "4" at 5630.9,3281.34 h60
  text "7.87mil (0.200mm)" at 5947.64,3281.34 h60
  text "PTH" at 6568.66,3281.34 h60
  text "Round" at 6812.59,3281.34 h60
  text "Top Layer - Bottom Layer" at 7172.49,3281.34 h60
  text "1" at 5630.9,3182.13 h60
  text "15.00mil (0.381mm)" at 5947.64,3182.13 h60
  text "PTH" at 6568.66,3182.13 h60
  text "Round" at 6812.59,3182.13 h60
  text "Top Layer - Bottom Layer" at 7172.49,3182.13 h60
  text "9" at 5630.9,3082.92 h60
  text "16.00mil (0.406mm)" at 5947.64,3082.92 h60
  text "PTH" at 6568.66,3082.92 h60
  text "Round" at 6812.59,3082.92 h60
  text "Top Layer - Bottom Layer" at 7172.49,3082.92 h60
  text "2" at 5630.9,2983.71 h60
  text "30.00mil (0.762mm)" at 5947.64,2983.71 h60
  text "PTH" at 6568.66,2983.71 h60
  text "Round" at 6812.59,2983.71 h60
  text "Top Layer - Bottom Layer" at 7172.49,2983.71 h60
  text "15" at 5630.9,2884.5 h60
  text "37.99mil (0.965mm)" at 5947.64,2884.5 h60
  text "PTH" at 6568.66,2884.5 h60
  text "Round" at 6812.59,2884.5 h60
  text "Top Layer - Bottom Layer" at 7172.49,2884.5 h60
  text "2" at 5630.9,2785.29 h60
  text "80.00mil (2.032mm)" at 5947.64,2785.29 h60
  text "PTH" at 6568.66,2785.29 h60
  text "Round" at 6812.59,2785.29 h60
  text "Top Layer - Bottom Layer" at 7172.49,2785.29 h60
  text "33 Total" at 5630.9,2686.07 h60
  text ".Layer_Name" at 577,-858.49 h60
M17 Embedded Cavity:
  text ".Layer_Name" at 577,-858.49 h60
M18 Embedded Assembly:
  text ".Layer_Name" at 577,-858.49 h60
M19 Embedded Keepout:
  text ".Layer_Name" at 577,-858.49 h60

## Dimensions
60,10 to 1330,0 on Top Layer
0,-400 to 1000,-400 on M2 Board Dimensions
